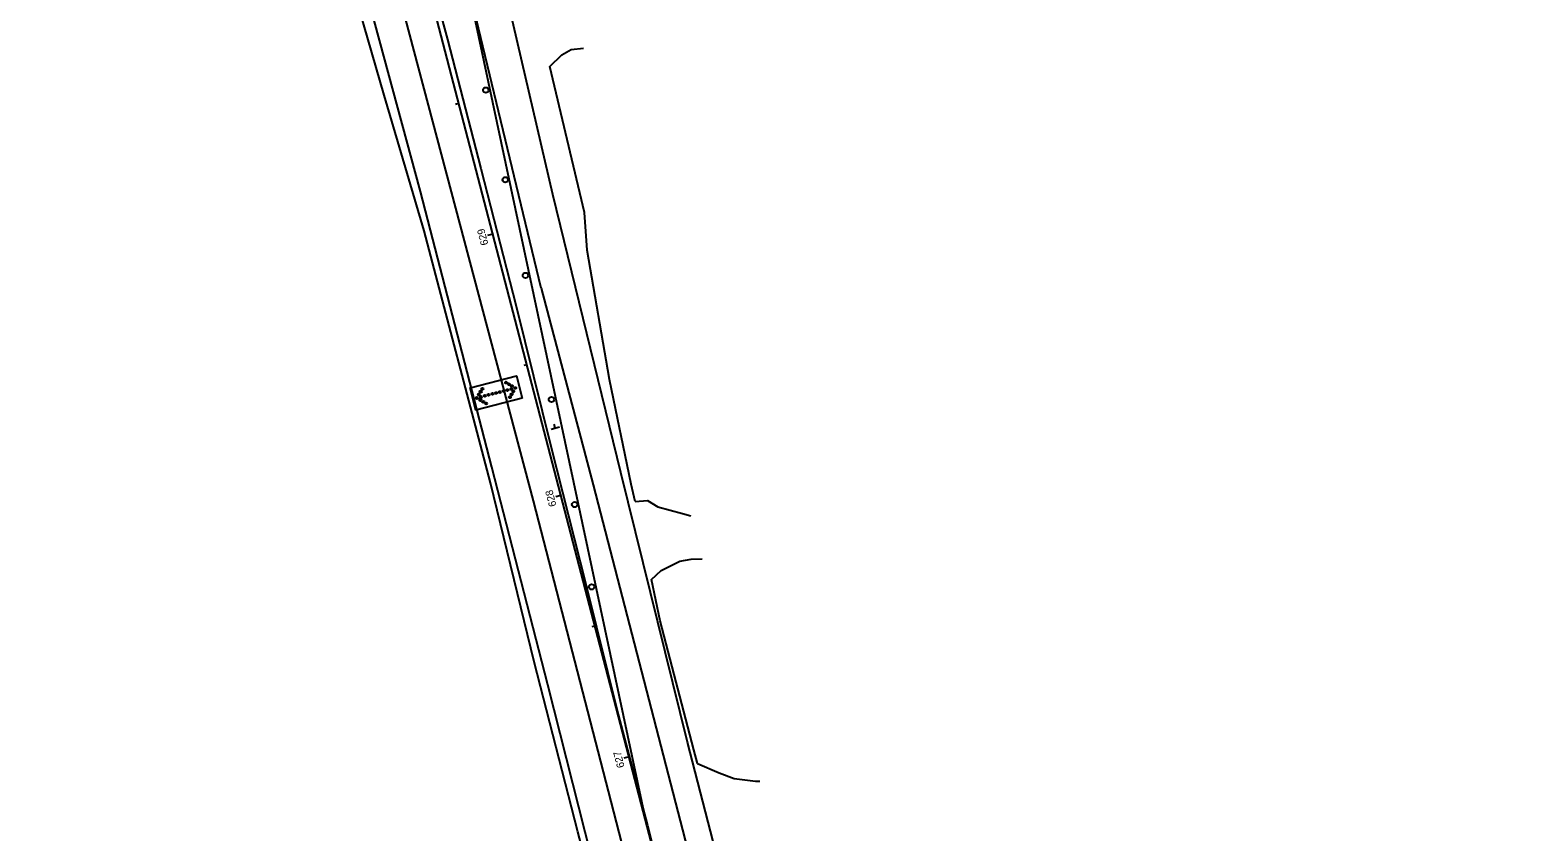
# Model space of a CAD drawing. Extents: x 171274 to 172251, y 454256 to 458569.
# Drawn here: x 171284 to 171842, y 455378 to 455675 of the extents above; entities that cross this region are included whole.
import ezdxf

# ---------------------------------------------------------------- set-up
doc = ezdxf.new("R2010")
doc.units = 0
for name, color, linetype in [('_CIVIL_CONSTRUCTION', 7, 'Continuous'), ('BR_X_Brg_Pad_Object', 7, 'Continuous'), ('BR_X_Gen_Approach_Slab', 7, 'Continuous'), ('BR_X_Rail_Object', 7, 'Continuous'), ('BR_X_Slab_Hidden', 7, 'Continuous'), ('BR_X_Sub_Backwall', 7, 'Continuous'), ('PV_P_Saw_Cut_Line', 7, 'Continuous'), ('SC_Scratch2', 7, 'Continuous'), ('UT_X_Water_Cells', 7, 'Continuous'), ('VG_X_Shrub_Line_Lt', 7, 'Continuous')]:
    doc.layers.add(name, color=color, linetype=linetype)

msp = doc.modelspace()

# ---------------------------------------------------------------- linework, layer by layer
at = {"layer": '_CIVIL_CONSTRUCTION'}
for q in [(171283.69, 456257.09), (171395.21, 455829.41)]:
    msp.add_line((171701.51, 454654.7), q, dxfattribs=at)
at = {"layer": 'BR_X_Brg_Pad_Object'}
for points in [[(171503.18, 455323.76), (171475.49, 455432.87), (171454.72, 455513.46), (171428.26, 455615.62), (171406.35, 455696.78), (171384.57, 455774.72), (171362.67, 455854.98), (171344.52, 455938.3), (171332.13, 456031.02), (171327.13, 456113.56), (171327.94, 456170.26), (171336.25, 456240.13)], [(171552.92, 455312.25), (171527.2, 455411.62), (171502.46, 455511.52), (171477.38, 455614.49), (171452.58, 455720.96), (171430.11, 455820.63), (171418.58, 455881.68), (171408.49, 455943.41), (171401.05, 456007.44), (171398.69, 456085.97), (171402.37, 456161.63), (171409.79, 456217.67)]]:
    msp.add_lwpolyline(points, dxfattribs=at)
at = {"layer": 'BR_X_Gen_Approach_Slab'}
msp.add_lwpolyline([(171372.41, 456249.06), (171365.59, 456208.9), (171361.9, 456180.52), (171358.94, 456147.75), (171357.35, 456099.47), (171358.68, 456055.61), (171363.09, 456004.12), (171368.78, 455963.12), (171376.92, 455917.74), (171388.16, 455864.82), (171402.87, 455806.41), (171418.61, 455743.92), (171438.27, 455671.9), (171450.64, 455624.13), (171463.74, 455573.1), (171476.6, 455521.3), (171489.49, 455470.21), (171501.56, 455421.89), (171512.39, 455380.78), (171524.4, 455333.79)], dxfattribs=at)
at = {"layer": 'BR_X_Rail_Object'}
for centre in [(171452.48, 455653.15), (171459.7, 455619.94), (171467.18, 455584.52), (171476.8, 455538.55), (171485.41, 455499.62), (171491.7, 455469.15)]:
    msp.add_circle(centre, 1, dxfattribs=at)
at = {"layer": 'BR_X_Slab_Hidden'}
for p, q in [((171476.67, 455527.62), (171479.76, 455528.42)), ((171478.22, 455528.02), (171477.84, 455529.47))]:
    msp.add_line(p, q, dxfattribs=at)
msp.add_lwpolyline([(171465.97, 455539.08), (171448.79, 455534.6), (171446.64, 455542.84), (171463.82, 455547.32)], close=True, dxfattribs=at)
for centre in [(171450.59, 455541.47), (171451.21, 455542.52), (171449.21, 455539.11), (171449.95, 455540.38), (171450.48, 455538.36), (171450.62, 455539.48), (171451.57, 455537.72), (171452.12, 455539.87), (171452.62, 455537.11), (171453.53, 455540.24), (171454.95, 455540.61)]:
    msp.add_circle(centre, 0.375, dxfattribs=at)
for centre in [(171457.66, 455541.31), (171459.08, 455541.68), (171459.99, 455544.81), (171460.49, 455542.05), (171461.04, 455544.2), (171461.99, 455542.44), (171462.13, 455543.56), (171462.66, 455541.54), (171463.4, 455542.81), (171456.31, 455540.96), (171461.4, 455539.4), (171462.02, 455540.45)]:
    msp.add_ellipse(centre, major_axis=(-0.363, -0.095), ratio=0.999351, dxfattribs=at)
at = {"layer": 'BR_X_Sub_Backwall'}
msp.add_line((171511.85, 455382.07), (171444.08, 455700.27), dxfattribs=at)
at = {"layer": 'PV_P_Saw_Cut_Line'}
for points in [[(171558.29, 455107.46), (171557.48, 455110.64), (171540.93, 455172.92), (171510.71, 455286.81), (171486.61, 455378.45), (171470.46, 455441.39), (171454.22, 455507.71), (171429.71, 455601.02), (171414.88, 455651.31), (171387.7, 455745.41), (171360.93, 455847.8), (171341.64, 455927.77), (171327.71, 456008.91), (171320.5, 456092.02), (171319.84, 456141.55), (171327.18, 456222.76), (171334.15, 456270.38), (171334.45, 456271.77)], [(171507.77, 455500.75), (171506.4, 455507.19), (171498.29, 455545.99), (171490.1, 455593.91), (171489.05, 455607.77), (171476.26, 455661.91)], [(171530.92, 455403.79), (171529.61, 455408.8), (171517.14, 455456.58), (171513.89, 455471.93)]]:
    msp.add_lwpolyline(points, dxfattribs=at)
at = {"layer": 'SC_Scratch2'}
for points in [[(171606.9, 456713.08), (171537.84, 456634.83), (171514.38, 456602.92), (171481.72, 456555.36), (171461.08, 456521.63), (171441.58, 456486.99), (171424.04, 456451.38), (171408.15, 456415.38), (171394.36, 456378.7), (171381.63, 456341.12), (171371.07, 456303.24), (171361.56, 456265.59), (171354.26, 456227.23), (171348.62, 456187.8), (171344.87, 456148.4), (171343.42, 456109.47), (171343.88, 456070.6), (171348.16, 456014.58), (171355.27, 455960.53), (171369.03, 455890.22), (171386.9, 455814.22), (171470.04, 455501.07), (171508.5, 455352.39)], [(171472.94, 455579.79), (171449.73, 455676.12), (171434.2, 455742.49), (171417.65, 455817.01), (171409.54, 455855.66), (171396.62, 455926.7), (171388.55, 455991.19), (171385.59, 456030.86), (171384.04, 456092.24), (171385.52, 456132), (171388.97, 456170.87), (171399.27, 456243.93), (171412.62, 456299.43), (171430.57, 456357.84), (171452.53, 456413.92), (171486.74, 456481.97), (171521.83, 456540.12), (171563.53, 456599.56), (171612.4, 456658.42), (171636.48, 456684.91)], [(171472.94, 455579.79), (171492.29, 455506.9), (171530.75, 455358.19), (171581.19, 455165.63), (171667.81, 454828.72), (171739.52, 454564.63), (171774.65, 454453.78), (171842.22, 454266.94)]]:
    msp.add_lwpolyline(points, dxfattribs=at)
at = {"layer": 'UT_X_Water_Cells'}
for points in [[(171476.26, 455661.91), (171480.69, 455666.22), (171484.09, 455668.24), (171488.72, 455668.62)], [(171507.77, 455500.75), (171512.4, 455501.15), (171516.24, 455498.84), (171525.4, 455496.29), (171528.39, 455495.44)], [(171513.89, 455471.93), (171517.47, 455475.25), (171524.36, 455478.66), (171528.55, 455479.43), (171532.63, 455479.6)], [(171530.92, 455403.79), (171538.91, 455400.32), (171544.51, 455398.21), (171552.43, 455397.19), (171553.95, 455397.22)]]:
    msp.add_lwpolyline(points, dxfattribs=at)
at = {"layer": 'VG_X_Shrub_Line_Lt'}
for p, q in [((171442.46, 455648.18), (171441.3, 455647.87)), ((171455.08, 455599.79), (171453.14, 455599.29)), ((171467.7, 455551.41), (171466.53, 455551.11)), ((171480.31, 455503.03), (171478.38, 455502.52)), ((171492.93, 455454.65), (171491.76, 455454.34)), ((171505.54, 455406.26), (171503.61, 455405.76))]:
    msp.add_line(p, q, dxfattribs=at)

# ---------------------------------------------------------------- texts
for s, p in [('629', (171453.47, 455596.04)), ('628', (171478.71, 455499.25)), ('627', (171503.94, 455402.5))]:
    msp.add_text(s, height=2.8, rotation=104.6143, dxfattribs=at).set_placement(p)

doc.saveas('drawing.dxf')
